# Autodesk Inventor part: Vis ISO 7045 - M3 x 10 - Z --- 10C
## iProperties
Created: 2011-01
Part Number: Vis ISO 7045 - M3 x 10 - Z --- 10C
Document SubType Name: Modeling
Designer: eric
Density: 1 g/cm^3
Mass: 0.115635 g
Surface Area: 1.81976 cm^2
Volume: 0.115635 cm^3
Author: eric
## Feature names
1. Base1
